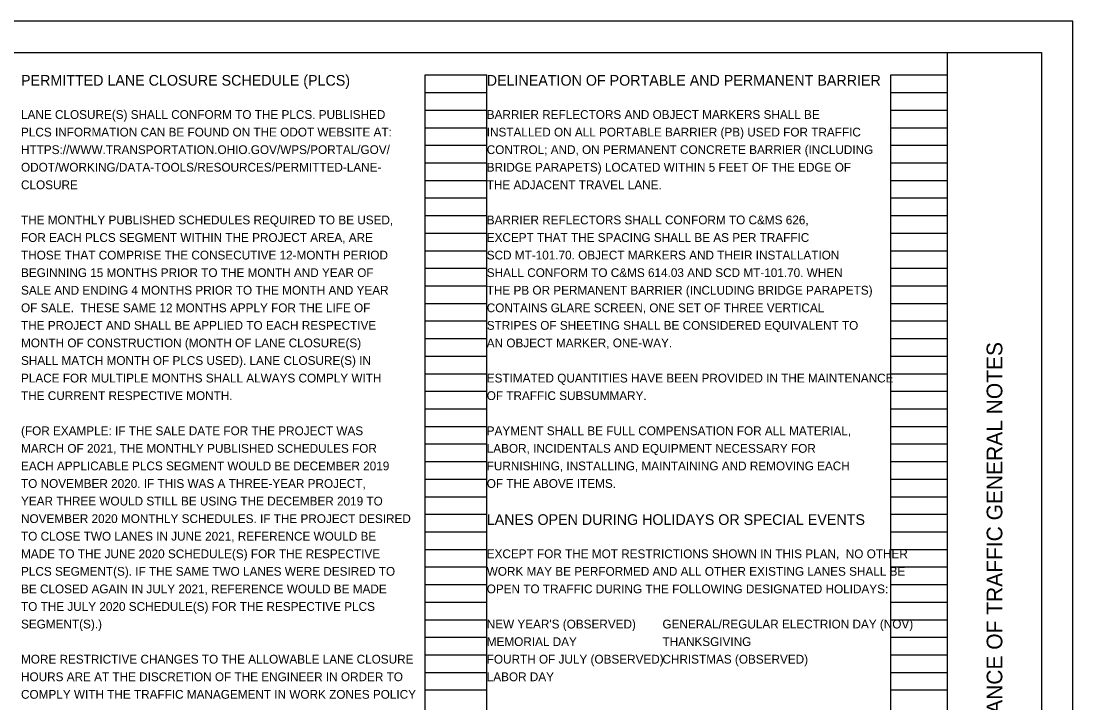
# Model space of a CAD drawing. Extents: x 0 to 34, y 0 to 22.
# Drawn here: x 17.24 to 34, y 11.13 to 22 of the extents above; entities that cross this region are included whole.
import ezdxf

# ---------------------------------------------------------------- set-up
doc = ezdxf.new("R2010")
doc.units = 0
for name, color, linetype in [('SH_Border', 7, 'Continuous'), ('SH_Cut_Line', 7, 'Continuous'), ('SH_Data', 7, 'Continuous'), ('SH_Text', 7, 'Continuous')]:
    doc.layers.add(name, color=color, linetype=linetype)

msp = doc.modelspace()

# ---------------------------------------------------------------- linework, layer by layer
at = {"layer": 'SH_Border'}
msp.add_line((32, 0.5), (32, 21.5), dxfattribs=at)
msp.add_lwpolyline([(1.5, 21.5), (33.5, 21.5), (33.5, 0.5), (1.5, 0.5)], close=True, dxfattribs=at)
at = {"layer": 'SH_Cut_Line'}
msp.add_lwpolyline([(0, 0), (34, 0), (34, 22), (0, 22)], close=True, dxfattribs=at)
at = {"layer": 'SH_Data'}
for p, q in [((23.68, 0.98), (23.68, 21.14)), ((23.68, 21.14), (24.66, 21.14)), ((24.66, 0.98), (24.66, 21.14)), ((31.1, 0.98), (31.1, 21.14)), ((31.1, 21.14), (32, 21.14)), ((32, 0.98), (32, 21.14)), ((23.68, 20.86), (24.66, 20.86)), ((31.1, 20.86), (32, 20.86)), ((23.68, 20.58), (24.66, 20.58)), ((31.1, 20.58), (32, 20.58)), ((23.68, 20.3), (24.66, 20.3)), ((31.1, 20.3), (32, 20.3)), ((23.68, 20.02), (24.66, 20.02)), ((31.1, 20.02), (32, 20.02)), ((23.68, 19.74), (24.66, 19.74)), ((31.1, 19.74), (32, 19.74)), ((23.68, 19.46), (24.66, 19.46)), ((31.1, 19.46), (32, 19.46)), ((23.68, 19.18), (24.66, 19.18)), ((31.1, 19.18), (32, 19.18)), ((23.68, 18.9), (24.66, 18.9)), ((31.1, 18.9), (32, 18.9)), ((23.68, 18.62), (24.66, 18.62)), ((31.1, 18.62), (32, 18.62)), ((23.68, 18.34), (24.66, 18.34)), ((31.1, 18.34), (32, 18.34)), ((23.68, 18.06), (24.66, 18.06)), ((31.1, 18.06), (32, 18.06)), ((23.68, 17.78), (24.66, 17.78)), ((31.1, 17.78), (32, 17.78)), ((23.68, 17.5), (24.66, 17.5)), ((31.1, 17.5), (32, 17.5)), ((23.68, 17.22), (24.66, 17.22)), ((31.1, 17.22), (32, 17.22)), ((23.68, 16.94), (24.66, 16.94)), ((31.1, 16.94), (32, 16.94)), ((23.68, 16.66), (24.66, 16.66)), ((31.1, 16.66), (32, 16.66)), ((23.68, 16.38), (24.66, 16.38)), ((31.1, 16.38), (32, 16.38)), ((23.68, 16.1), (24.66, 16.1)), ((31.1, 16.1), (32, 16.1)), ((23.68, 15.82), (24.66, 15.82)), ((31.1, 15.82), (32, 15.82)), ((23.68, 15.54), (24.66, 15.54)), ((31.1, 15.54), (32, 15.54)), ((23.68, 15.26), (24.66, 15.26)), ((31.1, 15.26), (32, 15.26)), ((23.68, 14.98), (24.66, 14.98)), ((31.1, 14.98), (32, 14.98)), ((23.68, 14.7), (24.66, 14.7)), ((31.1, 14.7), (32, 14.7)), ((23.68, 14.42), (24.66, 14.42)), ((31.1, 14.42), (32, 14.42)), ((23.68, 14.14), (24.66, 14.14)), ((31.1, 14.14), (32, 14.14)), ((23.68, 13.86), (24.66, 13.86)), ((31.1, 13.86), (32, 13.86)), ((23.68, 13.58), (24.66, 13.58)), ((31.1, 13.58), (32, 13.58)), ((23.68, 13.3), (24.66, 13.3)), ((31.1, 13.3), (32, 13.3)), ((23.68, 13.02), (24.66, 13.02)), ((31.1, 13.02), (32, 13.02)), ((23.68, 12.74), (24.66, 12.74)), ((31.1, 12.74), (32, 12.74)), ((23.68, 12.46), (24.66, 12.46)), ((31.1, 12.46), (32, 12.46)), ((23.68, 12.18), (24.66, 12.18)), ((31.1, 12.18), (32, 12.18)), ((23.68, 11.9), (24.66, 11.9)), ((31.1, 11.9), (32, 11.9)), ((23.68, 11.62), (24.66, 11.62)), ((31.1, 11.62), (32, 11.62)), ((23.68, 11.34), (24.66, 11.34)), ((31.1, 11.34), (32, 11.34))]:
    msp.add_line(p, q, dxfattribs=at)

# ---------------------------------------------------------------- texts
msp.add_text('MAINTENANCE OF TRAFFIC GENERAL NOTES', height=0.25, rotation=90, dxfattribs=at).set_placement((32.875, 9.455))
at = {"layer": 'SH_Text'}
for s, height, p in [('PERMITTED LANE CLOSURE SCHEDULE (PLCS)', 0.17, (17.24, 20.97)), ('DELINEATION OF PORTABLE AND PERMANENT BARRIER', 0.17, (24.66, 20.97)), ('LANE CLOSURE(S) SHALL CONFORM TO THE PLCS. PUBLISHED', 0.14, (17.24, 20.44)), ('BARRIER REFLECTORS AND OBJECT MARKERS SHALL BE', 0.14, (24.66, 20.44)), ('PLCS INFORMATION CAN BE FOUND ON THE ODOT WEBSITE AT:', 0.14, (17.24, 20.16)), ('INSTALLED ON ALL PORTABLE BARRIER (PB) USED FOR TRAFFIC', 0.14, (24.66, 20.16)), ('HTTPS://WWW.TRANSPORTATION.OHIO.GOV/WPS/PORTAL/GOV/', 0.14, (17.24, 19.88)), ('CONTROL; AND, ON PERMANENT CONCRETE BARRIER (INCLUDING', 0.14, (24.66, 19.88)), ('ODOT/WORKING/DATA-TOOLS/RESOURCES/PERMITTED-LANE-', 0.14, (17.24, 19.6)), ('BRIDGE PARAPETS) LOCATED WITHIN 5 FEET OF THE EDGE OF', 0.14, (24.66, 19.6)), ('CLOSURE', 0.14, (17.24, 19.32)), ('THE ADJACENT TRAVEL LANE.', 0.14, (24.66, 19.32)), ('THE MONTHLY PUBLISHED SCHEDULES REQUIRED TO BE USED,', 0.14, (17.24, 18.76)), ('BARRIER REFLECTORS SHALL CONFORM TO C&MS 626,', 0.14, (24.66, 18.76)), ('FOR EACH PLCS SEGMENT WITHIN THE PROJECT AREA, ARE', 0.14, (17.24, 18.48)), ('EXCEPT THAT THE SPACING SHALL BE AS PER TRAFFIC', 0.14, (24.66, 18.48)), ('THOSE THAT COMPRISE THE CONSECUTIVE 12-MONTH PERIOD', 0.14, (17.24, 18.2)), ('SCD MT-101.70. OBJECT MARKERS AND THEIR INSTALLATION', 0.14, (24.66, 18.2)), ('BEGINNING 15 MONTHS PRIOR TO THE MONTH AND YEAR OF', 0.14, (17.24, 17.92)), ('SHALL CONFORM TO C&MS 614.03 AND SCD MT-101.70. WHEN', 0.14, (24.66, 17.92)), ('SALE AND ENDING 4 MONTHS PRIOR TO THE MONTH AND YEAR', 0.14, (17.24, 17.64)), ('THE PB OR PERMANENT BARRIER (INCLUDING BRIDGE PARAPETS)', 0.14, (24.66, 17.64)), ('OF SALE.  THESE SAME 12 MONTHS APPLY FOR THE LIFE OF', 0.14, (17.24, 17.36)), ('CONTAINS GLARE SCREEN, ONE SET OF THREE VERTICAL', 0.14, (24.66, 17.36)), ('THE PROJECT AND SHALL BE APPLIED TO EACH RESPECTIVE', 0.14, (17.24, 17.08)), ('STRIPES OF SHEETING SHALL BE CONSIDERED EQUIVALENT TO', 0.14, (24.66, 17.08)), ('MONTH OF CONSTRUCTION (MONTH OF LANE CLOSURE(S)', 0.14, (17.24, 16.8)), ('AN OBJECT MARKER, ONE-WAY.', 0.14, (24.66, 16.8)), ('SHALL MATCH MONTH OF PLCS USED). LANE CLOSURE(S) IN', 0.14, (17.24, 16.52)), ('PLACE FOR MULTIPLE MONTHS SHALL ALWAYS COMPLY WITH', 0.14, (17.24, 16.24)), ('ESTIMATED QUANTITIES HAVE BEEN PROVIDED IN THE MAINTENANCE ', 0.14, (24.66, 16.24)), ('THE CURRENT RESPECTIVE MONTH.', 0.14, (17.24, 15.96)), ('OF TRAFFIC SUBSUMMARY.', 0.14, (24.66, 15.96)), ('(FOR EXAMPLE: IF THE SALE DATE FOR THE PROJECT WAS', 0.14, (17.24, 15.4)), ('PAYMENT SHALL BE FULL COMPENSATION FOR ALL MATERIAL,', 0.14, (24.66, 15.4)), ('MARCH OF 2021, THE MONTHLY PUBLISHED SCHEDULES FOR', 0.14, (17.24, 15.12)), ('LABOR, INCIDENTALS AND EQUIPMENT NECESSARY FOR', 0.14, (24.66, 15.12)), ('EACH APPLICABLE PLCS SEGMENT WOULD BE DECEMBER 2019', 0.14, (17.24, 14.84)), ('FURNISHING, INSTALLING, MAINTAINING AND REMOVING EACH', 0.14, (24.66, 14.84)), ('TO NOVEMBER 2020. IF THIS WAS A THREE-YEAR PROJECT,', 0.14, (17.24, 14.56)), ('OF THE ABOVE ITEMS.', 0.14, (24.66, 14.56)), ('YEAR THREE WOULD STILL BE USING THE DECEMBER 2019 TO', 0.14, (17.24, 14.28)), ('NOVEMBER 2020 MONTHLY SCHEDULES. IF THE PROJECT DESIRED', 0.14, (17.24, 14)), ('LANES OPEN DURING HOLIDAYS OR SPECIAL EVENTS', 0.17, (24.66, 13.97)), ('TO CLOSE TWO LANES IN JUNE 2021, REFERENCE WOULD BE', 0.14, (17.24, 13.72)), ('MADE TO THE JUNE 2020 SCHEDULE(S) FOR THE RESPECTIVE', 0.14, (17.24, 13.44)), ('EXCEPT FOR THE MOT RESTRICTIONS SHOWN IN THIS PLAN,  NO OTHER ', 0.14, (24.66, 13.44)), ('PLCS SEGMENT(S). IF THE SAME TWO LANES WERE DESIRED TO', 0.14, (17.24, 13.16)), ('WORK MAY BE PERFORMED AND ALL OTHER EXISTING LANES SHALL BE ', 0.14, (24.66, 13.16)), ('BE CLOSED AGAIN IN JULY 2021, REFERENCE WOULD BE MADE', 0.14, (17.24, 12.88)), ('OPEN TO TRAFFIC DURING THE FOLLOWING DESIGNATED HOLIDAYS:', 0.14, (24.66, 12.88)), ('TO THE JULY 2020 SCHEDULE(S) FOR THE RESPECTIVE PLCS', 0.14, (17.24, 12.6)), ('SEGMENT(S).)', 0.14, (17.24, 12.32)), ("NEW YEAR'S (OBSERVED)", 0.14, (24.66, 12.32)), ('GENERAL/REGULAR ELECTRION DAY (NOV)', 0.14, (27.46, 12.32)), ('MEMORIAL DAY        ', 0.14, (24.66, 12.04)), ('THANKSGIVING', 0.14, (27.46, 12.04)), ('MORE RESTRICTIVE CHANGES TO THE ALLOWABLE LANE CLOSURE', 0.14, (17.24, 11.76)), ('FOURTH OF JULY (OBSERVED)', 0.14, (24.66, 11.76)), ('CHRISTMAS (OBSERVED)', 0.14, (27.46, 11.76)), ('HOURS ARE AT THE DISCRETION OF THE ENGINEER IN ORDER TO', 0.14, (17.24, 11.48)), ('LABOR DAY     ', 0.14, (24.66, 11.48)), ('COMPLY WITH THE TRAFFIC MANAGEMENT IN WORK ZONES POLICY', 0.14, (17.24, 11.2))]:
    msp.add_text(s, height=height, dxfattribs=at).set_placement(p)

doc.saveas('drawing.dxf')
